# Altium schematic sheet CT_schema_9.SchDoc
size 277 x 170 mm
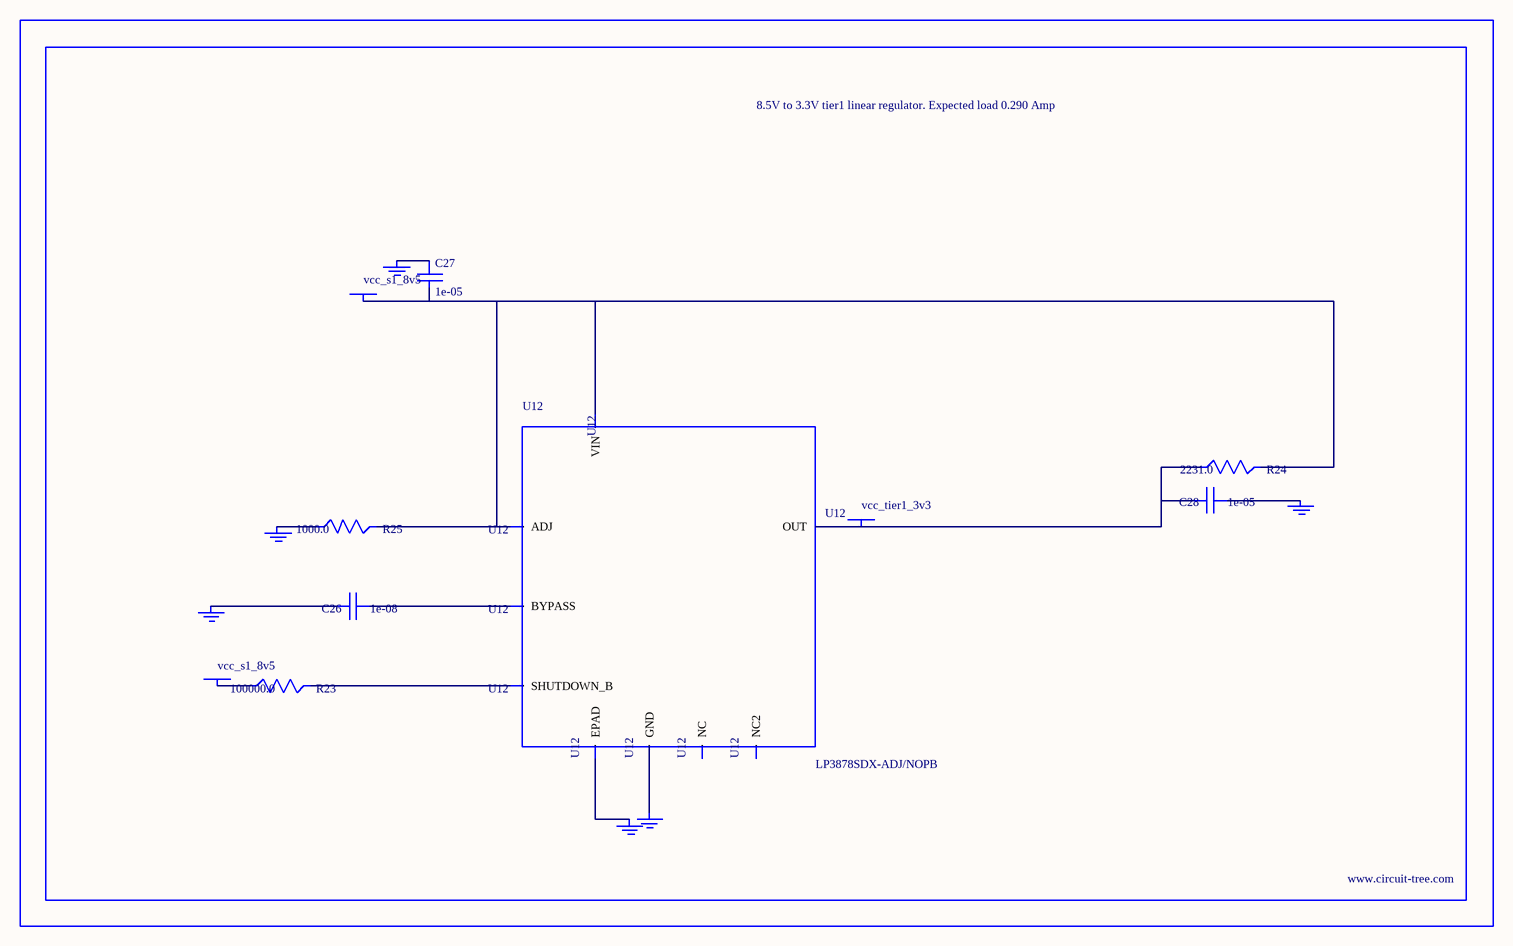
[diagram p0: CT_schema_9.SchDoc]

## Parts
BORDER8  (no value)
C26  1e-08  [C0402]
C27  1e-05  [C1206]
C28  1e-05  [C1210]
GND_INSTANCE_8_0  (no value)
GND_INSTANCE_8_1  (no value)
GND_INSTANCE_8_2  (no value)
GND_INSTANCE_8_3  (no value)
GND_INSTANCE_8_4  (no value)
GND_INSTANCE_8_5  (no value)
POWER_INSTANCE_8_0  vcc_s1_8v5
POWER_INSTANCE_8_1  vcc_s1_8v5
POWER_INSTANCE_8_2  vcc_tier1_3v3
R23  100000.0  [R0603]
R24  2231.0  [R0603]
R25  1000.0  [R0603]
U12  LP3878SDX-ADJ/NOPB  [WSON-8]

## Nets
NetC26_1: C26.1 U12.1(BYPASS)
NetC26_2: C26.2 GND_INSTANCE_8_0.0(GND)
NetC27_1: C27.1 GND_INSTANCE_8_1.0(GND)
NetC27_2: C27.2 POWER_INSTANCE_8_0.0(PWR) R24.2 R25.2 U12.4(VIN) U12.6(ADJ)
NetC28_1: C28.1 GND_INSTANCE_8_2.0(GND)
NetC28_2: C28.2 POWER_INSTANCE_8_2.0(PWR) R24.1 U12.5(OUT)
NetGND_INSTANCE_8_3_0: GND_INSTANCE_8_3.0(GND) R25.1
NetGND_INSTANCE_8_4_0: GND_INSTANCE_8_4.0(GND) U12.PAD(EPAD)
NetGND_INSTANCE_8_5_0: GND_INSTANCE_8_5.0(GND) U12.3(GND)
NetPOWER_INSTANCE_8_1_0: POWER_INSTANCE_8_1.0(PWR) R23.1
NetR23_2: R23.2 U12.8(SHUTDOWN_B)

Not connected (* = marked no-connect by the designer): U12 2(NC) 7(NC2)

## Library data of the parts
BORDER8 = BORDER_PAGE8
C26 = C0402C103K3RAC
C27 = C1206C106K3RACTU
C28 = GRM32DR61E106MA12L
GND_INSTANCE_8_0-GND_INSTANCE_8_5 = GND
POWER_INSTANCE_8_0-POWER_INSTANCE_8_2 = PWR
R23 = RC0603JR-07100KL
R24 = R24
R25 = RC0603JR-071KL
